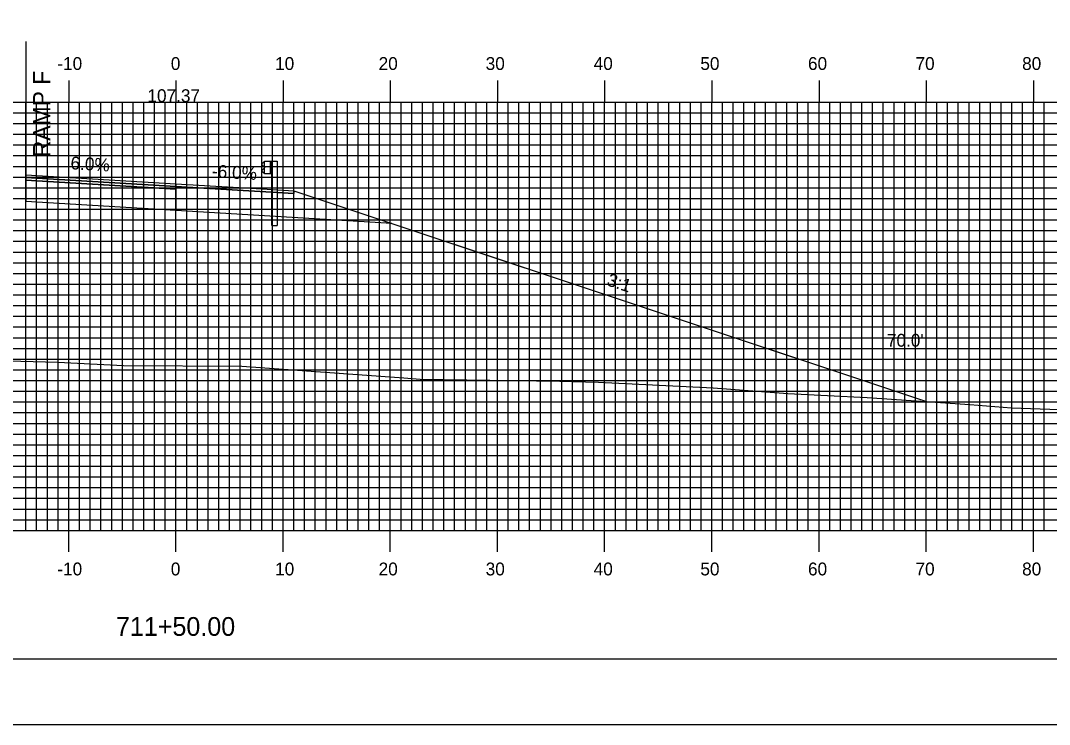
# Model space of a CAD drawing. Extents: x 855297 to 855640, y 364366 to 364586.
# Drawn here: x 855448.3 to 855544.3, y 364365.7 to 364431.4 of the extents above; entities that cross this region are included whole.
import ezdxf

# ---------------------------------------------------------------- set-up
doc = ezdxf.new("R2010")
doc.units = 0
for name, color, linetype in [('ANNOTATION', 7, 'Continuous'), ('BORDER', 7, 'Continuous'), ('D_Guardrail_Beam_Rt', 7, 'Continuous'), ('D_Roadway_Centerline', 7, 'Continuous'), ('D_Roadway_Centerline_Text', 7, 'Continuous'), ('D_Roadway_Edge_Shoulder', 7, 'Continuous'), ('D_Roadway_Edge_TW', 7, 'Continuous'), ('D_Roadway_Pavement', 7, 'Continuous'), ('D_Roadway_SlopeLines', 7, 'Continuous'), ('D_Roadway_SubGrade', 7, 'Continuous'), ('D_Text_Standard', 7, 'Continuous'), ('H_V ANNOTATION', 7, 'Continuous'), ('MAJOR', 7, 'Continuous'), ('MINOR', 7, 'Continuous'), ('PLOT BOUNDARY', 7, 'Continuous'), ('S_Roadway_Centerline', 7, 'Continuous')]:
    doc.layers.add(name, color=color, linetype=linetype)

msp = doc.modelspace()

# ---------------------------------------------------------------- linework, layer by layer
at = {"layer": 'BORDER'}
msp.add_lwpolyline([(855313.17, 364371.787), (855633.17, 364371.787), (855633.17, 364581.787), (855313.17, 364581.787)], close=True, dxfattribs=at)
at = {"layer": 'D_Guardrail_Beam_Rt'}
for p, q in [((855470.951, 364418.155), (855470.807, 364418.055)), ((855471.041, 364418.176), (855470.967, 364418.162)), ((855471.041, 364418.26), (855471.728, 364418.26)), ((855471.041, 364417.093), (855471.041, 364418.26)), ((855471.562, 364418.26), (855471.562, 364417.093)), ((855471.666, 364418.26), (855471.666, 364417.093)), ((855471.728, 364418.26), (855472.199, 364418.26)), ((855471.728, 364418.26), (855471.728, 364417.093)), ((855472.199, 364418.26), (855472.199, 364412.26)), ((855470.807, 364417.912), (855471.003, 364417.776)), ((855471.003, 364417.577), (855470.807, 364417.441)), ((855470.807, 364417.298), (855470.951, 364417.198)), ((855470.967, 364417.191), (855471.041, 364417.176)), ((855471.036, 364417.712), (855471.036, 364417.641)), ((855471.728, 364417.093), (855471.041, 364417.093)), ((855471.707, 364412.26), (855471.707, 364417.093)), ((855471.707, 364412.26), (855472.199, 364412.26))]:
    msp.add_line(p, q, dxfattribs=at)
for centre, major_axis, start_param, end_param in [((855470.858, 364417.984), (-0.0877, 0), 5.323254, 7.243116), ((855470.975, 364418.121), (-0.0417, 0), 4.907132, 5.323254), ((855470.858, 364417.369), (-0.0877, 0), 5.323254, 7.243116), ((855470.975, 364417.232), (-0.0417, 0), 0.959931, 1.376053), ((855470.957, 364417.712), (0.0789, 0), 0, 0.959931), ((855470.957, 364417.641), (0.0789, 0), 5.323254, 6.283185)]:
    msp.add_ellipse(centre, major_axis=major_axis, ratio=0.995501, start_param=start_param, end_param=end_param, dxfattribs=at)
at = {"layer": 'D_Roadway_Centerline'}
msp.add_lwpolyline([(855448.77, 364416.996), (855462.77, 364416.156), (855470.77, 364415.676), (855473.77, 364415.496), (855482.916, 364412.448), (855532.81, 364395.816)], dxfattribs=at)
at = {"layer": 'D_Roadway_Edge_Shoulder'}
msp.add_lwpolyline([(855462.77, 364416.156), (855470.77, 364415.676), (855470.77, 364415.676), (855473.77, 364415.496), (855473.77, 364415.246), (855462.77, 364415.906)], close=True, dxfattribs=at)
at = {"layer": 'D_Roadway_Edge_TW'}
msp.add_lwpolyline([(855448.77, 364416.996), (855462.77, 364416.156), (855462.77, 364415.906), (855448.77, 364416.746)], close=True, dxfattribs=at)
at = {"layer": 'D_Roadway_Pavement'}
msp.add_lwpolyline([(855448.77, 364416.746), (855462.77, 364415.906), (855462.77, 364415.656), (855448.77, 364416.496)], close=True, dxfattribs=at)
msp.add_lwpolyline([(855462.77, 364415.906), (855462.77, 364415.656)], dxfattribs=at)
msp.add_lwpolyline([(855462.77, 364415.906), (855462.77, 364415.656)], dxfattribs=at)
msp.add_lwpolyline([(855462.77, 364415.906), (855462.77, 364415.656)], dxfattribs=at)
at = {"layer": 'D_Roadway_SlopeLines'}
msp.add_lwpolyline([(855473.77, 364415.496), (855532.81, 364395.816)], dxfattribs=at)
at = {"layer": 'D_Roadway_SubGrade'}
msp.add_line((855448.77, 364429.454), (855448.77, 364414.496), dxfattribs=at)
for points in [[(855448.77, 364416.496), (855462.77, 364415.656), (855462.77, 364413.656), (855448.77, 364414.496)], [(855462.77, 364415.656), (855462.77, 364415.906), (855473.77, 364415.246), (855473.77, 364415.496), (855482.916, 364412.448), (855462.77, 364413.656)]]:
    msp.add_lwpolyline(points, close=True, dxfattribs=at)
at = {"layer": 'MAJOR'}
for p, q in [((855452.77, 364425.791), (855452.77, 364423.787)), ((855462.77, 364425.791), (855462.77, 364423.787)), ((855472.77, 364425.791), (855472.77, 364423.787)), ((855482.77, 364425.791), (855482.77, 364423.787)), ((855492.77, 364425.791), (855492.77, 364423.787)), ((855502.77, 364425.791), (855502.77, 364423.787)), ((855512.77, 364425.791), (855512.77, 364423.787)), ((855522.77, 364425.791), (855522.77, 364423.787)), ((855532.77, 364425.791), (855532.77, 364423.787)), ((855542.77, 364425.791), (855542.77, 364423.787)), ((855322.77, 364423.787), (855602.77, 364423.787)), ((855322.77, 364423.787), (855602.77, 364423.787)), ((855452.77, 364383.787), (855452.77, 364423.787)), ((855462.77, 364383.787), (855462.77, 364423.787)), ((855472.77, 364383.787), (855472.77, 364423.787)), ((855482.77, 364383.787), (855482.77, 364423.787)), ((855492.77, 364383.787), (855492.77, 364423.787)), ((855502.77, 364383.787), (855502.77, 364423.787)), ((855512.77, 364383.787), (855512.77, 364423.787)), ((855522.77, 364383.787), (855522.77, 364423.787)), ((855532.77, 364383.787), (855532.77, 364423.787)), ((855542.77, 364383.787), (855542.77, 364423.787)), ((855322.77, 364418.787), (855602.77, 364418.787)), ((855322.77, 364413.787), (855602.77, 364413.787)), ((855322.77, 364408.787), (855602.77, 364408.787)), ((855322.77, 364403.787), (855602.77, 364403.787)), ((855322.77, 364398.787), (855602.77, 364398.787)), ((855322.77, 364393.787), (855602.77, 364393.787)), ((855322.77, 364388.787), (855602.77, 364388.787)), ((855322.77, 364383.787), (855602.77, 364383.787)), ((855322.77, 364383.787), (855602.77, 364383.787)), ((855452.77, 364381.783), (855452.77, 364383.787)), ((855462.77, 364381.783), (855462.77, 364383.787)), ((855472.77, 364381.783), (855472.77, 364383.787)), ((855482.77, 364381.783), (855482.77, 364383.787)), ((855492.77, 364381.783), (855492.77, 364383.787)), ((855502.77, 364381.783), (855502.77, 364383.787)), ((855512.77, 364381.783), (855512.77, 364383.787)), ((855522.77, 364381.783), (855522.77, 364383.787)), ((855532.77, 364381.783), (855532.77, 364383.787)), ((855542.77, 364381.783), (855542.77, 364383.787))]:
    msp.add_line(p, q, dxfattribs=at)
at = {"layer": 'MINOR'}
for p, q in [((855448.77, 364383.787), (855448.77, 364423.787)), ((855449.77, 364383.787), (855449.77, 364423.787)), ((855450.77, 364383.787), (855450.77, 364423.787)), ((855451.77, 364383.787), (855451.77, 364423.787)), ((855453.77, 364383.787), (855453.77, 364423.787)), ((855454.77, 364383.787), (855454.77, 364423.787)), ((855455.77, 364383.787), (855455.77, 364423.787)), ((855456.77, 364383.787), (855456.77, 364423.787)), ((855457.77, 364383.787), (855457.77, 364423.787)), ((855458.77, 364383.787), (855458.77, 364423.787)), ((855459.77, 364383.787), (855459.77, 364423.787)), ((855460.77, 364383.787), (855460.77, 364423.787)), ((855461.77, 364383.787), (855461.77, 364423.787)), ((855463.77, 364383.787), (855463.77, 364423.787)), ((855464.77, 364383.787), (855464.77, 364423.787)), ((855465.77, 364383.787), (855465.77, 364423.787)), ((855466.77, 364383.787), (855466.77, 364423.787)), ((855467.77, 364383.787), (855467.77, 364423.787)), ((855468.77, 364383.787), (855468.77, 364423.787)), ((855469.77, 364383.787), (855469.77, 364423.787)), ((855470.77, 364383.787), (855470.77, 364423.787)), ((855471.77, 364383.787), (855471.77, 364423.787)), ((855473.77, 364383.787), (855473.77, 364423.787)), ((855474.77, 364383.787), (855474.77, 364423.787)), ((855475.77, 364383.787), (855475.77, 364423.787)), ((855476.77, 364383.787), (855476.77, 364423.787)), ((855477.77, 364383.787), (855477.77, 364423.787)), ((855478.77, 364383.787), (855478.77, 364423.787)), ((855479.77, 364383.787), (855479.77, 364423.787)), ((855480.77, 364383.787), (855480.77, 364423.787)), ((855481.77, 364383.787), (855481.77, 364423.787)), ((855483.77, 364383.787), (855483.77, 364423.787)), ((855484.77, 364383.787), (855484.77, 364423.787)), ((855485.77, 364383.787), (855485.77, 364423.787)), ((855486.77, 364383.787), (855486.77, 364423.787)), ((855487.77, 364383.787), (855487.77, 364423.787)), ((855488.77, 364383.787), (855488.77, 364423.787)), ((855489.77, 364383.787), (855489.77, 364423.787)), ((855490.77, 364383.787), (855490.77, 364423.787)), ((855491.77, 364383.787), (855491.77, 364423.787)), ((855493.77, 364383.787), (855493.77, 364423.787)), ((855494.77, 364383.787), (855494.77, 364423.787)), ((855495.77, 364383.787), (855495.77, 364423.787)), ((855496.77, 364383.787), (855496.77, 364423.787)), ((855497.77, 364383.787), (855497.77, 364423.787)), ((855498.77, 364383.787), (855498.77, 364423.787)), ((855499.77, 364383.787), (855499.77, 364423.787)), ((855500.77, 364383.787), (855500.77, 364423.787)), ((855501.77, 364383.787), (855501.77, 364423.787)), ((855503.77, 364383.787), (855503.77, 364423.787)), ((855504.77, 364383.787), (855504.77, 364423.787)), ((855505.77, 364383.787), (855505.77, 364423.787)), ((855506.77, 364383.787), (855506.77, 364423.787)), ((855507.77, 364383.787), (855507.77, 364423.787)), ((855508.77, 364383.787), (855508.77, 364423.787)), ((855509.77, 364383.787), (855509.77, 364423.787)), ((855510.77, 364383.787), (855510.77, 364423.787)), ((855511.77, 364383.787), (855511.77, 364423.787)), ((855513.77, 364383.787), (855513.77, 364423.787)), ((855514.77, 364383.787), (855514.77, 364423.787)), ((855515.77, 364383.787), (855515.77, 364423.787)), ((855516.77, 364383.787), (855516.77, 364423.787)), ((855517.77, 364383.787), (855517.77, 364423.787)), ((855518.77, 364383.787), (855518.77, 364423.787)), ((855519.77, 364383.787), (855519.77, 364423.787)), ((855520.77, 364383.787), (855520.77, 364423.787)), ((855521.77, 364383.787), (855521.77, 364423.787)), ((855523.77, 364383.787), (855523.77, 364423.787)), ((855524.77, 364383.787), (855524.77, 364423.787)), ((855525.77, 364383.787), (855525.77, 364423.787)), ((855526.77, 364383.787), (855526.77, 364423.787)), ((855527.77, 364383.787), (855527.77, 364423.787)), ((855528.77, 364383.787), (855528.77, 364423.787)), ((855529.77, 364383.787), (855529.77, 364423.787)), ((855530.77, 364383.787), (855530.77, 364423.787)), ((855531.77, 364383.787), (855531.77, 364423.787)), ((855533.77, 364383.787), (855533.77, 364423.787)), ((855534.77, 364383.787), (855534.77, 364423.787)), ((855535.77, 364383.787), (855535.77, 364423.787)), ((855536.77, 364383.787), (855536.77, 364423.787)), ((855537.77, 364383.787), (855537.77, 364423.787)), ((855538.77, 364383.787), (855538.77, 364423.787)), ((855539.77, 364383.787), (855539.77, 364423.787)), ((855540.77, 364383.787), (855540.77, 364423.787)), ((855541.77, 364383.787), (855541.77, 364423.787)), ((855543.77, 364383.787), (855543.77, 364423.787)), ((855322.77, 364422.787), (855602.77, 364422.787)), ((855322.77, 364421.787), (855602.77, 364421.787)), ((855322.77, 364420.787), (855602.77, 364420.787)), ((855322.77, 364419.787), (855602.77, 364419.787)), ((855322.77, 364417.787), (855602.77, 364417.787)), ((855322.77, 364416.787), (855602.77, 364416.787)), ((855322.77, 364415.787), (855602.77, 364415.787)), ((855322.77, 364414.787), (855602.77, 364414.787)), ((855322.77, 364412.787), (855602.77, 364412.787)), ((855322.77, 364411.787), (855602.77, 364411.787)), ((855322.77, 364410.787), (855602.77, 364410.787)), ((855322.77, 364409.787), (855602.77, 364409.787)), ((855322.77, 364407.787), (855602.77, 364407.787)), ((855322.77, 364406.787), (855602.77, 364406.787)), ((855322.77, 364405.787), (855602.77, 364405.787)), ((855322.77, 364404.787), (855602.77, 364404.787)), ((855322.77, 364402.787), (855602.77, 364402.787)), ((855322.77, 364401.787), (855602.77, 364401.787)), ((855322.77, 364400.787), (855602.77, 364400.787)), ((855322.77, 364399.787), (855602.77, 364399.787)), ((855322.77, 364397.787), (855602.77, 364397.787)), ((855322.77, 364396.787), (855602.77, 364396.787)), ((855322.77, 364395.787), (855602.77, 364395.787)), ((855322.77, 364394.787), (855602.77, 364394.787)), ((855322.77, 364392.787), (855602.77, 364392.787)), ((855322.77, 364391.787), (855602.77, 364391.787)), ((855322.77, 364390.787), (855602.77, 364390.787)), ((855322.77, 364389.787), (855602.77, 364389.787)), ((855322.77, 364387.787), (855602.77, 364387.787)), ((855322.77, 364386.787), (855602.77, 364386.787)), ((855322.77, 364385.787), (855602.77, 364385.787)), ((855322.77, 364384.787), (855602.77, 364384.787))]:
    msp.add_line(p, q, dxfattribs=at)
at = {"layer": 'PLOT BOUNDARY'}
msp.add_lwpolyline([(855296.983, 364365.669), (855636.983, 364365.669), (855636.983, 364585.669), (855296.983, 364585.669)], close=True, dxfattribs=at)
at = {"layer": 'S_Roadway_Centerline'}
msp.add_lwpolyline([(855441.38, 364399.777), (855451.748, 364399.499), (855457.886, 364399.204), (855468.908, 364399.12), (855484.043, 364398.039), (855485.55, 364397.924), (855498.597, 364397.721), (855502.203, 364397.624), (855512.902, 364397.109), (855519.858, 364396.564), (855527.261, 364396.185), (855536.843, 364395.549), (855540.718, 364395.237), (855553.232, 364394.807), (855554.484, 364394.762), (855559.671, 364394.5), (855569.897, 364393.924), (855572.999, 364393.776), (855586.352, 364392.936), (855595.353, 364392.6), (855602.77, 364392.285)], dxfattribs=at)

# ---------------------------------------------------------------- texts
at = {"layer": 'ANNOTATION'}
for s, height, rotation, p in [('RAMP F', 1.6, 90, (855451.031, 364418.634)), ('6.0%', 1.2, 356.56637, (855452.903, 364417.521)), ('-6.0%', 1.2, 356.56637, (855466.104, 364416.76)), ('3:1', 1.2, 341.56505, (855502.894, 364406.697))]:
    msp.add_text(s, height=height, rotation=rotation, dxfattribs=at).set_placement(p)
at = {"layer": 'D_Roadway_Centerline_Text'}
msp.add_text('107.37', height=1.2, dxfattribs=at).set_placement((855460.105, 364423.785))
at = {"layer": 'D_Text_Standard'}
msp.add_text("70.0'", height=1.2, dxfattribs=at).set_placement((855529.106, 364400.943))
at = {"layer": 'H_V ANNOTATION'}
for s, height, p in [('-10', 1.2, (855451.7, 364426.787)), ('0', 1.2, (855462.288, 364426.787)), ('10', 1.2, (855472.021, 364426.787)), ('20', 1.2, (855481.678, 364426.787)), ('30', 1.2, (855491.667, 364426.787)), ('40', 1.2, (855501.742, 364426.787)), ('50', 1.2, (855511.699, 364426.787)), ('60', 1.2, (855521.742, 364426.787)), ('70', 1.2, (855531.774, 364426.787)), ('80', 1.2, (855541.721, 364426.787)), ('-10', 1.2, (855451.7, 364379.587)), ('0', 1.2, (855462.288, 364379.587)), ('10', 1.2, (855472.021, 364379.587)), ('20', 1.2, (855481.678, 364379.587)), ('30', 1.2, (855491.667, 364379.587)), ('40', 1.2, (855501.742, 364379.587)), ('50', 1.2, (855511.699, 364379.587)), ('60', 1.2, (855521.742, 364379.587)), ('70', 1.2, (855531.774, 364379.587)), ('80', 1.2, (855541.721, 364379.587)), ('711+50.00', 1.75, (855457.167, 364373.943))]:
    msp.add_text(s, height=height, dxfattribs=at).set_placement(p)

doc.saveas('drawing.dxf')
